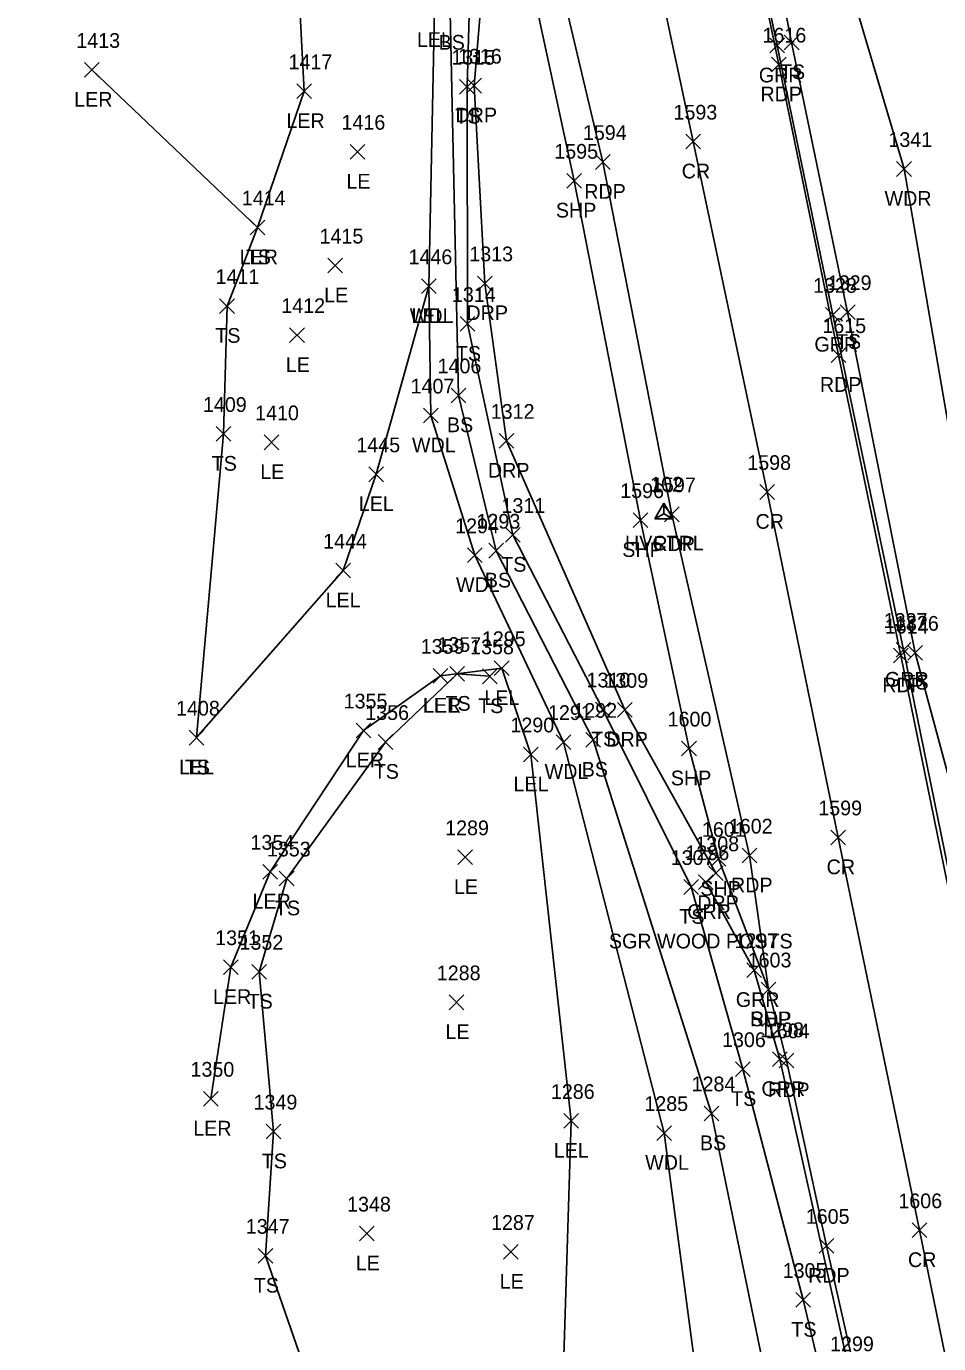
# Model space of a CAD drawing. Extents: x 1545627 to 1546562, y 571176 to 576667.
# Drawn here: x 1545980.7 to 1546104.7, y 572214.6 to 572393.7 of the extents above; entities that cross this region are included whole.
import ezdxf

# ---------------------------------------------------------------- set-up
doc = ezdxf.new("R2010")
doc.units = 0
for name, color, linetype in [('C_A', 7, 'Continuous'), ('C_I', 7, 'Continuous'), ('CPSM', 7, 'Continuous'), ('L_A', 7, 'Continuous'), ('L_I', 7, 'Continuous'), ('L_TIC', 7, 'Continuous'), ('LARO', 7, 'Continuous'), ('LAWA', 7, 'Continuous'), ('LELB', 7, 'Continuous'), ('P_A', 7, 'Continuous'), ('P_I', 7, 'Continuous'), ('P_TIC', 7, 'Continuous'), ('PET', 7, 'Continuous'), ('PRC', 7, 'Continuous'), ('PSP', 7, 'Continuous'), ('R_A', 7, 'Continuous'), ('R_C', 7, 'Continuous'), ('R_I', 7, 'Continuous'), ('R_TIC', 7, 'Continuous'), ('RDP', 7, 'Continuous'), ('RGR', 7, 'Continuous')]:
    doc.layers.add(name, color=color, linetype=linetype)

msp = doc.modelspace()

# ---------------------------------------------------------------- linework, layer by layer
at = {"layer": 'CPSM'}
for p, q in [((1546066.09, 572326.7), (1546067.34, 572328.87)), ((1546068.59, 572326.7), (1546067.34, 572328.87)), ((1546067.34, 572327.42), (1546067.34, 572328.87)), ((1546066.09, 572326.7), (1546067.34, 572327.42)), ((1546066.09, 572326.7), (1546068.59, 572326.7)), ((1546067.34, 572327.42), (1546067.34, 572327.42)), ((1546067.34, 572327.42), (1546068.59, 572326.7))]:
    msp.add_line(p, q, dxfattribs=at)
at = {"layer": 'L_TIC'}
for points in [[(1546083.69, 572390.49), (1546085.69, 572392.49)], [(1546085.69, 572390.49), (1546083.69, 572392.49)], [(1545988.59, 572386.75), (1545990.59, 572388.75)], [(1545990.59, 572386.75), (1545988.59, 572388.75)], [(1546017.44, 572383.85), (1546019.44, 572385.85)], [(1546019.44, 572383.85), (1546017.44, 572385.85)], [(1546039.57, 572384.46), (1546041.57, 572386.46)], [(1546041.57, 572384.46), (1546039.57, 572386.46)], [(1546024.7, 572375.62), (1546026.7, 572377.62)], [(1546026.7, 572375.62), (1546024.7, 572377.62)], [(1546098.96, 572373.28), (1546100.96, 572375.28)], [(1546100.96, 572373.28), (1546098.96, 572375.28)], [(1546011.09, 572365.33), (1546013.09, 572367.33)], [(1546013.09, 572365.33), (1546011.09, 572367.33)], [(1546011.09, 572365.33), (1546013.09, 572367.33)], [(1546013.09, 572365.33), (1546011.09, 572367.33)], [(1546021.65, 572360.15), (1546023.65, 572362.15)], [(1546023.65, 572360.15), (1546021.65, 572362.15)], [(1546034.37, 572357.34), (1546036.37, 572359.34)], [(1546036.37, 572357.34), (1546034.37, 572359.34)], [(1546034.37, 572357.34), (1546036.37, 572359.34)], [(1546036.37, 572357.34), (1546034.37, 572359.34)], [(1546006.95, 572354.65), (1546008.95, 572356.65)], [(1546008.95, 572354.65), (1546006.95, 572356.65)], [(1546091.3, 572353.82), (1546093.3, 572355.82)], [(1546093.3, 572353.82), (1546091.3, 572355.82)], [(1546039.65, 572352.21), (1546041.65, 572354.21)], [(1546041.65, 572352.21), (1546039.65, 572354.21)], [(1546016.46, 572350.69), (1546018.46, 572352.69)], [(1546018.46, 572350.69), (1546016.46, 572352.69)], [(1546038.4, 572342.5), (1546040.4, 572344.5)], [(1546040.4, 572342.5), (1546038.4, 572344.5)], [(1546034.67, 572339.76), (1546036.67, 572341.76)], [(1546036.67, 572339.76), (1546034.67, 572341.76)], [(1546006.46, 572337.26), (1546008.46, 572339.26)], [(1546008.46, 572337.26), (1546006.46, 572339.26)], [(1546012.98, 572336.12), (1546014.98, 572338.12)], [(1546014.98, 572336.12), (1546012.98, 572338.12)], [(1546027.22, 572331.77), (1546029.22, 572333.77)], [(1546029.22, 572331.77), (1546027.22, 572333.77)], [(1546045.81, 572323.53), (1546047.81, 572325.53)], [(1546047.81, 572323.53), (1546045.81, 572325.53)], [(1546043.55, 572321.39), (1546045.55, 572323.39)], [(1546045.55, 572321.39), (1546043.55, 572323.39)], [(1546040.65, 572320.77), (1546042.65, 572322.77)], [(1546042.65, 572320.77), (1546040.65, 572322.77)], [(1546022.72, 572318.68), (1546024.72, 572320.68)], [(1546024.72, 572318.68), (1546022.72, 572320.68)], [(1546100.48, 572307.51), (1546102.48, 572309.51)], [(1546102.48, 572307.51), (1546100.48, 572309.51)], [(1546044.28, 572305.42), (1546046.28, 572307.42)], [(1546046.28, 572305.42), (1546044.28, 572307.42)], [(1546035.98, 572304.38), (1546037.98, 572306.38)], [(1546037.98, 572304.38), (1546035.98, 572306.38)], [(1546035.98, 572304.38), (1546037.98, 572306.38)], [(1546037.98, 572304.38), (1546035.98, 572306.38)], [(1546038.24, 572304.63), (1546040.24, 572306.63)], [(1546040.24, 572304.63), (1546038.24, 572306.63)], [(1546042.68, 572304.31), (1546044.68, 572306.31)], [(1546044.68, 572304.31), (1546042.68, 572306.31)], [(1546058.02, 572299.8), (1546060.02, 572301.8)], [(1546060.02, 572299.8), (1546058.02, 572301.8)], [(1546025.5, 572296.94), (1546027.5, 572298.94)], [(1546027.5, 572296.94), (1546025.5, 572298.94)], [(1546002.8, 572295.97), (1546004.8, 572297.97)], [(1546004.8, 572295.97), (1546002.8, 572297.97)], [(1546002.8, 572295.97), (1546004.8, 572297.97)], [(1546004.8, 572295.97), (1546002.8, 572297.97)], [(1546028.49, 572295.38), (1546030.49, 572297.38)], [(1546030.49, 572295.38), (1546028.49, 572297.38)], [(1546052.7, 572295.37), (1546054.7, 572297.37)], [(1546054.7, 572295.37), (1546052.7, 572297.37)], [(1546056.72, 572295.67), (1546058.72, 572297.67)], [(1546058.72, 572295.67), (1546056.72, 572297.67)], [(1546056.72, 572295.67), (1546058.72, 572297.67)], [(1546058.72, 572295.67), (1546056.72, 572297.67)], [(1546048.25, 572293.69), (1546050.25, 572295.69)], [(1546050.25, 572293.69), (1546048.25, 572295.69)], [(1546039.3, 572279.71), (1546041.3, 572281.71)], [(1546041.3, 572279.71), (1546039.3, 572281.71)], [(1546012.83, 572277.74), (1546014.83, 572279.74)], [(1546014.83, 572277.74), (1546012.83, 572279.74)], [(1546015.06, 572276.82), (1546017.06, 572278.82)], [(1546017.06, 572276.82), (1546015.06, 572278.82)], [(1546070.02, 572275.67), (1546072.02, 572277.67)], [(1546072.02, 572275.67), (1546070.02, 572277.67)], [(1546007.46, 572264.77), (1546009.46, 572266.77)], [(1546009.46, 572264.77), (1546007.46, 572266.77)], [(1546011.34, 572264.14), (1546013.34, 572266.14)], [(1546013.34, 572264.14), (1546011.34, 572266.14)], [(1546038.15, 572259.99), (1546040.15, 572261.99)], [(1546040.15, 572259.99), (1546038.15, 572261.99)], [(1546077.06, 572250.91), (1546079.06, 572252.91)], [(1546079.06, 572250.91), (1546077.06, 572252.91)], [(1546004.77, 572246.88), (1546006.77, 572248.88)], [(1546006.77, 572246.88), (1546004.77, 572248.88)], [(1546072.78, 572244.89), (1546074.78, 572246.89)], [(1546074.78, 572244.89), (1546072.78, 572246.89)], [(1546013.26, 572242.42), (1546015.26, 572244.42)], [(1546015.26, 572242.42), (1546013.26, 572244.42)], [(1546053.72, 572243.86), (1546055.72, 572245.86)], [(1546055.72, 572243.86), (1546053.72, 572245.86)], [(1546066.36, 572242.22), (1546068.36, 572244.22)], [(1546068.36, 572242.22), (1546066.36, 572244.22)], [(1546025.96, 572228.55), (1546027.96, 572230.55)], [(1546027.96, 572228.55), (1546025.96, 572230.55)], [(1546012.19, 572225.53), (1546014.19, 572227.53)], [(1546014.19, 572225.53), (1546012.19, 572227.53)], [(1546045.52, 572226.06), (1546047.52, 572228.06)], [(1546047.52, 572226.06), (1546045.52, 572228.06)], [(1546085.25, 572219.53), (1546087.25, 572221.53)], [(1546087.25, 572219.53), (1546085.25, 572221.53)]]:
    msp.add_lwpolyline(points, dxfattribs=at)
at = {"layer": 'LARO'}
for points in [[(1546003.8, 572296.97), (1546023.72, 572319.68), (1546028.22, 572332.77), (1546035.37, 572358.34), (1546036.13, 572395.88), (1546037.14, 572418.47), (1546035.66, 572443.9), (1546032.56, 572464.13), (1546022.86, 572503.7), (1546023.08, 572512.5), (1546018.73, 572511.87), (1546018.26, 572497.05)], [(1545989.59, 572387.75), (1546012.09, 572366.33), (1546018.44, 572384.85), (1546017.67, 572399.68), (1546012.33, 572402.4), (1545998.77, 572410.1), (1545995.43, 572416.6), (1545999.36, 572423.01), (1546017.16, 572423.17), (1546022.83, 572451.45), (1546022.18, 572459.73), (1546023.12, 572478.43), (1546017.42, 572489.77), (1546018.26, 572497.05)], [(1546005.77, 572247.88), (1546008.46, 572265.77), (1546013.83, 572278.74), (1546026.5, 572297.94), (1546036.98, 572305.38)], [(1546061.88, 572087.81), (1546067.17, 572106.31), (1546070.63, 572137.24), (1546070.36, 572157.28), (1546064.88, 572171.54), (1546050.76, 572183.34), (1546053.43, 572202.66), (1546054.72, 572244.86), (1546049.25, 572294.69), (1546045.28, 572306.42), (1546036.98, 572305.38)]]:
    msp.add_lwpolyline(points, dxfattribs=at)
at = {"layer": 'LAWA'}
for points in [[(1546132.7, 572194.89), (1546123.45, 572251.15), (1546111.94, 572304.9), (1546099.96, 572374.28), (1546086.11, 572421.03), (1546079.85, 572451.63), (1546071.91, 572496.17), (1546064.39, 572527.58), (1546058.59, 572548.65), (1546052.09, 572585.93), (1546038.43, 572619.67), (1546027.83, 572654.92), (1546018.77, 572685.67), (1546005.34, 572728.46), (1545993.81, 572765.21), (1545980.93, 572799.99)], [(1546084.88, 572141.02), (1546075.58, 572176.11), (1546072.22, 572206.65), (1546067.36, 572243.22), (1546053.7, 572296.37), (1546041.65, 572321.77), (1546035.67, 572340.76), (1546035.37, 572358.34)]]:
    msp.add_lwpolyline(points, dxfattribs=at)
at = {"layer": 'LELB'}
for points in [[(1546125.53, 572192.44), (1546119.79, 572223.12), (1546112.54, 572267.48), (1546101.48, 572308.51), (1546092.3, 572354.82), (1546084.69, 572391.49), (1546079.39, 572418.94), (1546072.14, 572452.75), (1546063.27, 572495.37), (1546056.18, 572525.93), (1546052.45, 572548.06), (1546043.75, 572580.7), (1546033.1, 572617.26), (1546022.59, 572652.85), (1546012.21, 572685.19), (1545999.02, 572724.09), (1545985.45, 572763.44), (1545973.14, 572794.95)], [(1546057.72, 572296.67), (1546044.55, 572322.39), (1546039.4, 572343.5), (1546038.27, 572395.5), (1546040.06, 572418.12), (1546038.19, 572444), (1546032.75, 572474.34), (1546026.06, 572504.78), (1546024.23, 572513.12), (1546018.98, 572530.73), (1546011.95, 572554.6), (1546002.16, 572589.36), (1546002.67, 572591.46), (1546001.66, 572594.58), (1546000.81, 572597.18), (1545999.9, 572600.86), (1545993.99, 572622.54), (1545979.25, 572672.26), (1545965.55, 572712.15), (1545952.14, 572749.58), (1545938.38, 572786.62)], [(1546100.91, 572156.04), (1546094.34, 572186.85), (1546086.25, 572220.53), (1546078.06, 572251.91), (1546071.02, 572276.67), (1546059.02, 572300.8), (1546046.81, 572324.53), (1546040.65, 572353.21), (1546040.57, 572385.46), (1546041.51, 572418.18), (1546039.81, 572443.48)], [(1546003.8, 572296.97), (1546007.46, 572338.26), (1546007.95, 572355.65), (1546012.09, 572366.33)], [(1546023.82, 572195.83), (1546013.19, 572226.53), (1546014.26, 572243.42), (1546012.34, 572265.14), (1546016.06, 572277.82), (1546029.49, 572296.38), (1546039.24, 572305.63), (1546043.68, 572305.31)], [(1546092.98, 572148.01), (1546087.88, 572176.73), (1546081.44, 572208.68), (1546073.78, 572245.89), (1546057.72, 572296.67)]]:
    msp.add_lwpolyline(points, dxfattribs=at)
at = {"layer": 'P_TIC'}
for points in [[(1546081.96, 572387.47), (1546083.96, 572389.47)], [(1546083.96, 572387.47), (1546081.96, 572389.47)], [(1546070.32, 572377), (1546072.32, 572379)], [(1546072.32, 572377), (1546070.32, 572379)], [(1546058.02, 572374.23), (1546060.02, 572376.23)], [(1546060.02, 572374.23), (1546058.02, 572376.23)], [(1546054.12, 572371.68), (1546056.12, 572373.68)], [(1546056.12, 572371.68), (1546054.12, 572373.68)], [(1546090.04, 572347.98), (1546092.04, 572349.98)], [(1546092.04, 572347.98), (1546090.04, 572349.98)], [(1546080.35, 572329.37), (1546082.35, 572331.37)], [(1546082.35, 572329.37), (1546080.35, 572331.37)], [(1546063.14, 572325.54), (1546065.14, 572327.54)], [(1546065.14, 572325.54), (1546063.14, 572327.54)], [(1546067.4, 572326.33), (1546069.4, 572328.33)], [(1546069.4, 572326.33), (1546067.4, 572328.33)], [(1546098.52, 572307.13), (1546100.52, 572309.13)], [(1546100.52, 572307.13), (1546098.52, 572309.13)], [(1546069.74, 572294.49), (1546071.74, 572296.49)], [(1546071.74, 572294.49), (1546069.74, 572296.49)], [(1546090.01, 572282.41), (1546092.01, 572284.41)], [(1546092.01, 572282.41), (1546090.01, 572284.41)], [(1546077.97, 572279.94), (1546079.97, 572281.94)], [(1546079.97, 572279.94), (1546077.97, 572281.94)], [(1546073.74, 572279.49), (1546075.74, 572281.49)], [(1546075.74, 572279.49), (1546073.74, 572281.49)], [(1546080.53, 572261.74), (1546082.53, 572263.74)], [(1546082.53, 572261.74), (1546080.53, 572263.74)], [(1546080.53, 572261.74), (1546082.53, 572263.74)], [(1546082.53, 572261.74), (1546080.53, 572263.74)], [(1546082.99, 572252.1), (1546084.99, 572254.1)], [(1546084.99, 572252.1), (1546082.99, 572254.1)], [(1546101.06, 572229), (1546103.06, 572231)], [(1546103.06, 572229), (1546101.06, 572231)], [(1546088.43, 572226.88), (1546090.43, 572228.88)], [(1546090.43, 572226.88), (1546088.43, 572228.88)]]:
    msp.add_lwpolyline(points, dxfattribs=at)
at = {"layer": 'PET'}
msp.add_lwpolyline([(1546019.19, 572549.75), (1546028.2, 572511.71), (1546038.29, 572467), (1546043.91, 572438.71), (1546048.46, 572419.83), (1546059.02, 572375.23), (1546068.4, 572327.33), (1546078.97, 572280.94), (1546081.53, 572262.74), (1546083.99, 572253.1), (1546089.43, 572227.88), (1546096.04, 572198.55), (1546104.44, 572159.78), (1546113.19, 572174.92), (1546122.63, 572188.98), (1546117.06, 572219.81), (1546108.58, 572263.74), (1546099.52, 572308.13), (1546091.04, 572348.98), (1546082.96, 572388.47), (1546076.51, 572419.41), (1546067.66, 572461.14), (1546060.5, 572495.35), (1546051.12, 572536.86)], dxfattribs=at)
at = {"layer": 'PRC'}
msp.add_lwpolyline([(1545789.97, 573149.91), (1545812.75, 573103.84), (1545835.71, 573057.35), (1545858.01, 573011.3), (1545880.3, 572964.26), (1545901.33, 572918.7), (1545921.74, 572873.14), (1545941.5, 572826.68), (1545959.26, 572783.14), (1545976.31, 572737.15), (1545992.66, 572690.86), (1546006.78, 572646.35), (1546020.38, 572601.27), (1546032.77, 572553.22), (1546041.68, 572514.93), (1546051.79, 572470.3), (1546061.81, 572422.58), (1546071.32, 572378), (1546081.35, 572330.37), (1546091.01, 572283.41), (1546102.06, 572230), (1546107.88, 572201.7), (1546113.19, 572174.92)], dxfattribs=at)
at = {"layer": 'PSP'}
msp.add_lwpolyline([(1546043.91, 572438.71), (1546045, 572419.76), (1546055.12, 572372.68), (1546064.14, 572326.54), (1546070.74, 572295.49), (1546074.74, 572280.49), (1546081.53, 572262.74)], dxfattribs=at)
at = {"layer": 'R_TIC'}
for points in [[(1546081.74, 572390.05), (1546083.74, 572392.05)], [(1546083.74, 572390.05), (1546081.74, 572392.05)], [(1546040.52, 572384.61), (1546042.52, 572386.61)], [(1546042.52, 572384.61), (1546040.52, 572386.61)], [(1546042, 572357.73), (1546044, 572359.73)], [(1546044, 572357.73), (1546042, 572359.73)], [(1546089.29, 572353.45), (1546091.29, 572355.45)], [(1546091.29, 572353.45), (1546089.29, 572355.45)], [(1546044.92, 572336.32), (1546046.92, 572338.32)], [(1546046.92, 572336.32), (1546044.92, 572338.32)], [(1546098.88, 572307.9), (1546100.88, 572309.9)], [(1546100.88, 572307.9), (1546098.88, 572309.9)], [(1546061.01, 572299.75), (1546063.01, 572301.75)], [(1546063.01, 572299.75), (1546061.01, 572301.75)], [(1546073.37, 572277.53), (1546075.37, 572279.53)], [(1546075.37, 572277.53), (1546073.37, 572279.53)], [(1546072.01, 572276.32), (1546074.01, 572278.32)], [(1546074.01, 572276.32), (1546072.01, 572278.32)], [(1546078.61, 572264.36), (1546080.61, 572266.36)], [(1546080.61, 572264.36), (1546078.61, 572266.36)], [(1546082.09, 572252.25), (1546084.09, 572254.25)], [(1546084.09, 572252.25), (1546082.09, 572254.25)]]:
    msp.add_lwpolyline(points, dxfattribs=at)
at = {"layer": 'RDP'}
msp.add_lwpolyline([(1546074.37, 572278.53), (1546062.01, 572300.75), (1546045.92, 572337.32), (1546043, 572358.73), (1546041.52, 572385.61), (1546044.25, 572418.19)], dxfattribs=at)
at = {"layer": 'RGR'}
for points in [[(1546122.9, 572190.91), (1546117.32, 572223.34), (1546108.74, 572265.6), (1546099.88, 572308.9), (1546090.29, 572354.45), (1546082.74, 572391.05), (1546076.81, 572419.12), (1546069.97, 572452.17), (1546060.89, 572495.21), (1546054.25, 572525.61), (1546048.91, 572547.32), (1546040.71, 572580.21), (1546030.58, 572616.09), (1546020.22, 572652.04), (1546009.86, 572685.1), (1545996.97, 572723.72), (1545983.08, 572762.48), (1545970.88, 572794.29)], [(1546073.01, 572277.32), (1546079.61, 572265.36), (1546083.09, 572253.25), (1546092.61, 572210.56), (1546099.36, 572179.54), (1546103.78, 572159.12)]]:
    msp.add_lwpolyline(points, dxfattribs=at)

# ---------------------------------------------------------------- texts
at = {"layer": 'C_A'}
msp.add_text('HVCTRL', height=2, dxfattribs=at).set_placement((1546062.04, 572322.42))
at = {"layer": 'C_I'}
msp.add_text('102', height=2, dxfattribs=at).set_placement((1546065.47, 572330.42))
at = {"layer": 'L_A'}
for s, p in [('LEL', (1546033.76, 572390.88)), ('BS', (1546036.71, 572390.5)), ('TS', (1546083.1, 572386.49)), ('LER', (1545987.18, 572382.75)), ('TS', (1546038.98, 572380.46)), ('LER', (1546016.02, 572379.85)), ('LE', (1546024.18, 572371.62)), ('WDR', (1546097.32, 572369.28)), ('LER', (1546009.67, 572361.33)), ('TS', (1546010.5, 572361.33)), ('LE', (1546021.14, 572356.15)), ('WDL', (1546032.79, 572353.34)), ('LEL', (1546033.01, 572353.34)), ('TS', (1546006.36, 572350.65)), ('TS', (1546090.71, 572349.82)), ('TS', (1546039.06, 572348.21)), ('LE', (1546015.95, 572346.69)), ('BS', (1546037.84, 572338.5)), ('WDL', (1546033.09, 572335.76)), ('TS', (1546005.87, 572333.26)), ('LE', (1546012.47, 572332.12)), ('LEL', (1546025.86, 572327.77)), ('TS', (1546045.22, 572319.53)), ('WDL', (1546039.07, 572316.77)), ('BS', (1546042.99, 572317.39)), ('LEL', (1546021.35, 572314.68)), ('TS', (1546099.89, 572303.51)), ('LEL', (1546042.92, 572301.42)), ('LER', (1546034.57, 572300.38)), ('LEL', (1546034.62, 572300.38)), ('TS', (1546037.65, 572300.63)), ('TS', (1546042.09, 572300.31)), ('TS', (1546057.43, 572295.8)), ('LER', (1546024.08, 572292.94)), ('LEL', (1546001.44, 572291.97)), ('TS', (1546002.21, 572291.97)), ('TS', (1546027.9, 572291.38)), ('WDL', (1546051.12, 572291.37)), ('BS', (1546056.16, 572291.67)), ('BS', (1546056.16, 572291.67)), ('LEL', (1546046.89, 572289.69)), ('LE', (1546038.79, 572275.71)), ('LER', (1546011.42, 572273.74)), ('TS', (1546014.47, 572272.82)), ('TS', (1546069.43, 572271.67)), ('LER', (1546006.04, 572260.77)), ('TS', (1546010.75, 572260.14)), ('LE', (1546037.64, 572255.99)), ('TS', (1546076.47, 572246.91)), ('LER', (1546003.36, 572242.88)), ('BS', (1546072.22, 572240.89)), ('LEL', (1546052.36, 572239.86)), ('TS', (1546012.67, 572238.42)), ('WDL', (1546064.78, 572238.22)), ('LE', (1546025.45, 572224.55)), ('TS', (1546011.6, 572221.53)), ('LE', (1546045.01, 572222.06)), ('TS', (1546084.65, 572215.53))]:
    msp.add_text(s, height=2, dxfattribs=at).set_placement(p)
at = {"layer": 'L_I'}
for s, p in [('1413', (1545987.47, 572390.75)), ('1417', (1546016.31, 572387.85)), ('1315', (1546038.44, 572388.46)), ('1416', (1546023.51, 572379.62)), ('1341', (1546097.84, 572377.28)), ('1414', (1546009.96, 572369.33)), ('1414', (1546009.96, 572369.33)), ('1415', (1546020.53, 572364.15)), ('1446', (1546032.62, 572361.34)), ('1446', (1546032.62, 572361.34)), ('1411', (1546006.39, 572358.65)), ('1329', (1546089.6, 572357.82)), ('1314', (1546038.52, 572356.21)), ('1412', (1546015.33, 572354.69)), ('1406', (1546036.57, 572346.5)), ('1407', (1546032.9, 572343.76)), ('1409', (1546004.68, 572341.26)), ('1410', (1546011.77, 572340.12)), ('1445', (1546025.53, 572335.77)), ('1311', (1546045.25, 572327.53)), ('1294', (1546038.96, 572324.77)), ('1293', (1546041.86, 572325.39)), ('1444', (1546021.02, 572322.68)), ('1326', (1546098.74, 572311.51)), ('1357', (1546036.54, 572308.63)), ('1295', (1546042.59, 572309.42)), ('1359', (1546034.28, 572308.38)), ('1359', (1546034.28, 572308.38)), ('1358', (1546040.99, 572308.31)), ('1310', (1546056.81, 572303.8)), ('1408', (1546001.03, 572299.97)), ('1408', (1546001.03, 572299.97)), ('1355', (1546023.8, 572300.94)), ('1292', (1546055.02, 572299.67)), ('1292', (1546055.02, 572299.67)), ('1356', (1546026.74, 572299.38)), ('1291', (1546051.57, 572299.37)), ('1290', (1546046.47, 572297.69)), ('1289', (1546037.6, 572283.71)), ('1354', (1546011.14, 572281.74)), ('1353', (1546013.37, 572280.82)), ('1307', (1546068.25, 572279.67)), ('1351', (1546006.34, 572268.77)), ('1352', (1546009.65, 572268.14)), ('1288', (1546036.46, 572263.99)), ('1306', (1546075.23, 572254.91)), ('1350', (1546002.99, 572250.88)), ('1286', (1546051.97, 572247.86)), ('1284', (1546071.09, 572248.89)), ('1349', (1546011.56, 572246.42)), ('1285', (1546064.67, 572246.22)), ('1348', (1546024.27, 572232.55)), ('1287', (1546043.83, 572230.06)), ('1347', (1546010.5, 572229.53)), ('1305', (1546083.47, 572223.53))]:
    msp.add_text(s, height=2, dxfattribs=at).set_placement(p)
at = {"layer": 'P_A'}
for s, p in [('RDP', (1546080.45, 572383.47)), ('CR', (1546069.75, 572373)), ('RDP', (1546056.5, 572370.23)), ('SHP', (1546052.65, 572367.68)), ('RDP', (1546088.53, 572343.98)), ('CR', (1546079.78, 572325.37)), ('SHP', (1546061.67, 572321.54)), ('RDP', (1546065.89, 572322.33)), ('RDP', (1546097.01, 572303.13)), ('SHP', (1546068.27, 572290.49)), ('CR', (1546089.44, 572278.41)), ('SHP', (1546072.28, 572275.49)), ('RDP', (1546076.45, 572275.94)), ('SHP', (1546079.07, 572257.74)), ('RDP', (1546079.02, 572257.74)), ('RDP', (1546081.48, 572248.1)), ('CR', (1546100.5, 572225)), ('RDP', (1546086.92, 572222.88))]:
    msp.add_text(s, height=2, dxfattribs=at).set_placement(p)
at = {"layer": 'P_I'}
for s, p in [('1616', (1546080.73, 572391.47)), ('1593', (1546068.63, 572381)), ('1594', (1546056.32, 572378.23)), ('1595', (1546052.43, 572375.68)), ('1615', (1546088.86, 572351.98)), ('1598', (1546078.66, 572333.37)), ('1597', (1546065.71, 572330.33)), ('1596', (1546061.39, 572329.54)), ('1614', (1546097.35, 572311.13)), ('1600', (1546067.83, 572298.49)), ('1599', (1546088.31, 572286.41)), ('1601', (1546072.49, 572283.49)), ('1602', (1546076.15, 572283.94)), ('1603', (1546078.71, 572265.74)), ('1603', (1546078.71, 572265.74)), ('1604', (1546081.17, 572256.1)), ('1606', (1546099.19, 572233)), ('1605', (1546086.61, 572230.88))]:
    msp.add_text(s, height=2, dxfattribs=at).set_placement(p)
at = {"layer": 'R_A'}
for s, p in [('GRR', (1546080.23, 572386.05)), ('DRP', (1546039.01, 572380.61)), ('DRP', (1546040.49, 572353.73)), ('GRR', (1546087.78, 572349.45)), ('DRP', (1546043.41, 572332.32)), ('GRR', (1546097.37, 572303.9)), ('DRP', (1546059.5, 572295.75)), ('DRP', (1546071.86, 572273.53)), ('GRR', (1546070.5, 572272.32)), ('GRR', (1546077.1, 572260.36)), ('GRR', (1546080.58, 572248.25))]:
    msp.add_text(s, height=2, dxfattribs=at).set_placement(p)
at = {"layer": 'R_C'}
msp.add_text('SGR WOOD POSTS', height=2, dxfattribs=at).set_placement((1546059.86, 572268.32))
at = {"layer": 'R_I'}
for s, p in [('1316', (1546039.34, 572388.61)), ('1313', (1546040.88, 572361.73)), ('1328', (1546087.6, 572357.45)), ('1312', (1546043.79, 572340.32)), ('1327', (1546097.19, 572311.9)), ('1309', (1546059.24, 572303.75)), ('1296', (1546070.26, 572280.32)), ('1308', (1546071.6, 572281.53)), ('1297', (1546076.92, 572268.36)), ('1298', (1546080.4, 572256.25)), ('1299', (1546089.91, 572213.56))]:
    msp.add_text(s, height=2, dxfattribs=at).set_placement(p)

doc.saveas('drawing.dxf')
